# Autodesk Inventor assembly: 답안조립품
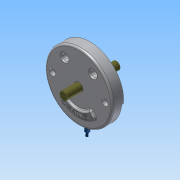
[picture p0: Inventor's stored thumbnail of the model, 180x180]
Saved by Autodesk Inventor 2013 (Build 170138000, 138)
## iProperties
Created: 2015-04
Part Number: 답안조립품
Document SubType Name: Assembly
Designer: Administrator
Author: Administrator
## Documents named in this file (9)
- C:\Users\Administrator\Desktop\450406V1027\답안조립품.iam
- C:\Users\Administrator\Desktop\450406V1027\본체.ipt
- C:\Users\Administrator\Desktop\450406V1027\축.ipt
- C:\Users\Administrator\Desktop\450406V1027\슬라이더2.ipt
- C:\Users\Administrator\Desktop\450406V1027\베어링62_22.ipt
- C:\Users\Administrator\Desktop\450406V1027\슬라이더.ipt
- C:\Users\Administrator\Desktop\450406V1027\평행핀.ipt
- C:\Users\Administrator\Desktop\450406V1027\멈춤링.ipt
- C:\Users\Administrator\Desktop\450406V1027\덮개.ipt
